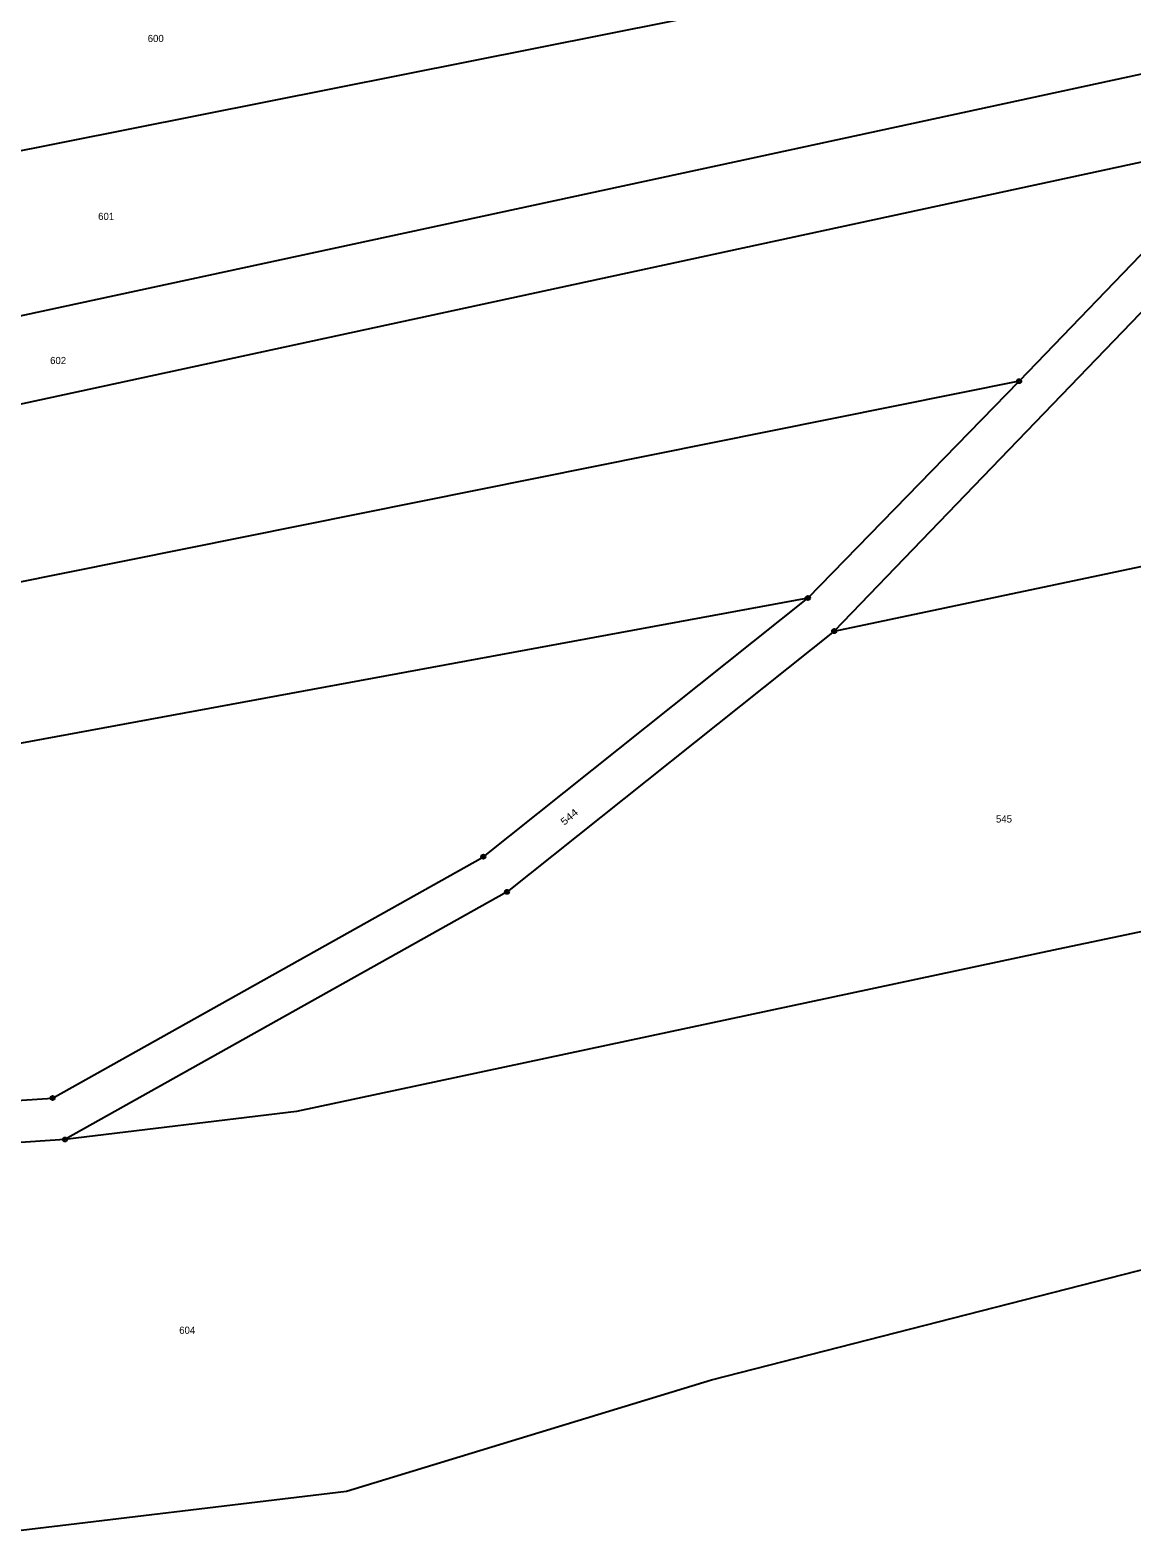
# Model space of a CAD drawing. Extents: x -719614 to -717765, y -1095834 to -1093862.
# Drawn here: x -719356.7 to -719095.8, y -1095522.4 to -1095165.2 of the extents above; entities that cross this region are included whole.
import ezdxf
from ezdxf.enums import TextEntityAlignment as Align

# ---------------------------------------------------------------- set-up
doc = ezdxf.new("R2010")
doc.units = 0
doc.header["$LTSCALE"] = 0.68
doc.layers.add('1', color=7, linetype='Continuous', lineweight=25)
doc.layers.add('8', color=7, linetype='Continuous', lineweight=25)
doc.layers.add('2', color=7, linetype='Continuous')

msp = doc.modelspace()

# ---------------------------------------------------------------- linework, layer by layer
at = {"layer": '1'}
for p, q in [((-719369.21, -1095195.79), (-719188.64, -1095159.84)), ((-719061.31, -1095168.69), (-719189.98, -1095196.44)), ((-719069.65, -1095191.3), (-719187.93, -1095216.84)), ((-719189.98, -1095196.44), (-719362.05, -1095233.55)), ((-719070.95, -1095194.83), (-719122.48, -1095248.36)), ((-719062.73, -1095199.98), (-719166.26, -1095307.55)), ((-719187.93, -1095216.84), (-719364.47, -1095254.96)), ((-719122.48, -1095248.36), (-719181.77, -1095260.28)), ((-719172.49, -1095299.73), (-719122.48, -1095248.36)), ((-719181.77, -1095260.28), (-719361.53, -1095296.42)), ((-719166.26, -1095307.55), (-718993, -1095270.99)), ((-719172.49, -1095299.73), (-719366.03, -1095335.41)), ((-719249.36, -1095361), (-719172.49, -1095299.73)), ((-719166.26, -1095307.55), (-719243.76, -1095369.33)), ((-719351.37, -1095418.17), (-719249.36, -1095361)), ((-719017.15, -1095362.51), (-719113.18, -1095382.94)), ((-719243.76, -1095369.33), (-719348.45, -1095428)), ((-719113.18, -1095382.94), (-719293.63, -1095421.33)), ((-719404.15, -1095421.65), (-719351.37, -1095418.17)), ((-719293.63, -1095421.33), (-719348.45, -1095428)), ((-719348.45, -1095428), (-719404.15, -1095431.67)), ((-719195.29, -1095484.97), (-719068.94, -1095452.55)), ((-719281.74, -1095511.29), (-719195.29, -1095484.97)), ((-719373.73, -1095522.37), (-719281.74, -1095511.29))]:
    msp.add_line(p, q, dxfattribs=at)
at = {"layer": '8'}
for centre, radius in [((-719122.48, -1095248.3599), 0.5), ((-719122.48, -1095248.3599), 0.0303), ((-719172.49, -1095299.7299), 0.5), ((-719172.49, -1095299.7299), 0.0303), ((-719166.26, -1095307.5499), 0.5), ((-719166.26, -1095307.5499), 0.0303), ((-719249.36, -1095360.9999), 0.5), ((-719249.36, -1095360.9999), 0.0303), ((-719243.76, -1095369.3299), 0.5), ((-719243.76, -1095369.3299), 0.0303), ((-719351.37, -1095418.1699), 0.5), ((-719351.37, -1095418.1699), 0.0303), ((-719348.45, -1095427.9999), 0.5), ((-719348.45, -1095427.9999), 0.0303)]:
    msp.add_circle(centre, radius, dxfattribs=at)

# ---------------------------------------------------------------- texts
at = {"layer": '2'}
for s, p in [('600', (-719326.959, -1095168.012)), ('601', (-719338.699, -1095210.162)), ('602', (-719350.079, -1095244.302)), ('545', (-719126.049, -1095352.912)), ('604', (-719319.499, -1095474.042))]:
    msp.add_text(s, height=1.7, dxfattribs=at).set_placement(p, align=Align.CENTER)
at = {"layer": '2', "width": 1.2}
msp.add_text('544', height=1.7, rotation=40, dxfattribs=at).set_placement((-719228.4664, -1095352.2192), align=Align.CENTER)

doc.saveas('drawing.dxf')
